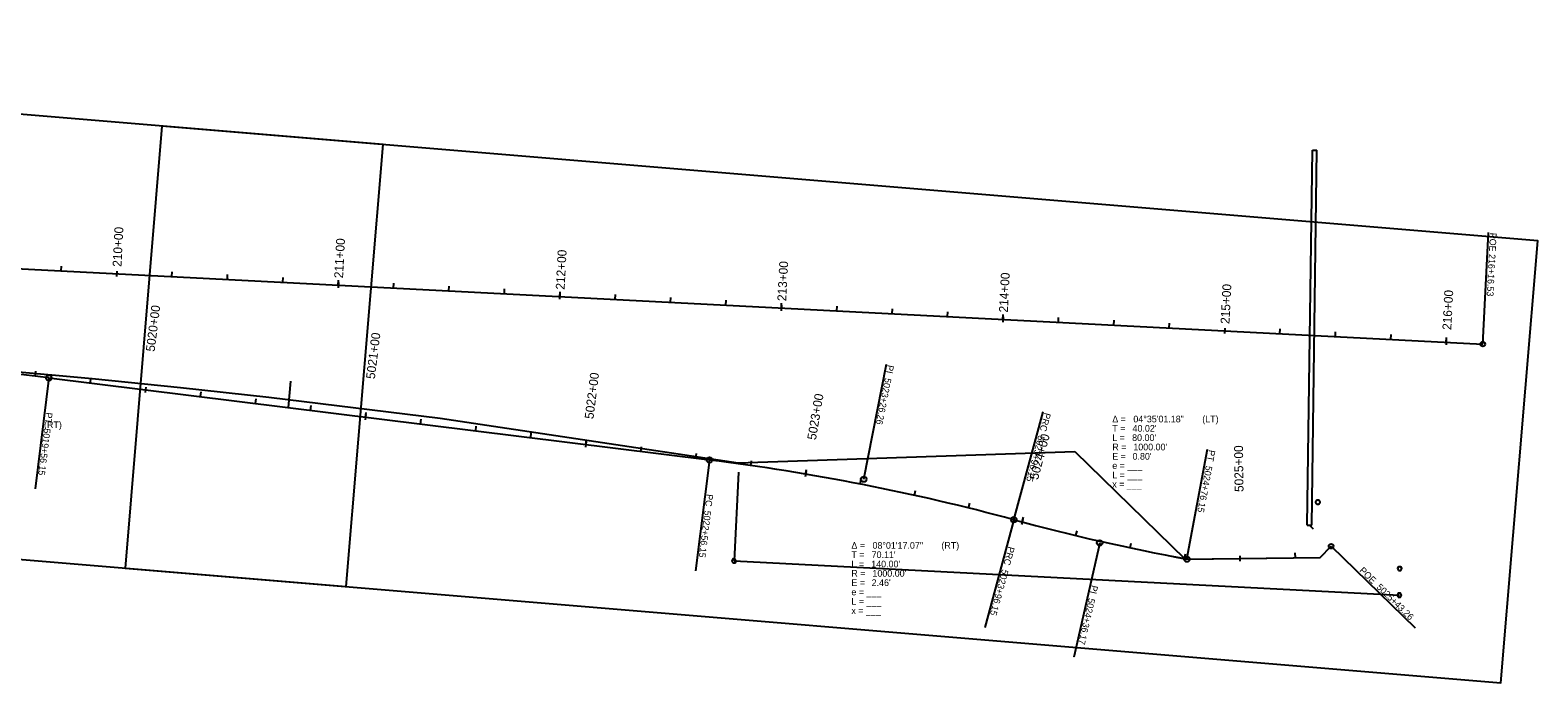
# Model space of a CAD drawing. Extents: x 20500393 to 20505339, y 7953466 to 7954298.
# Drawn here: x 20504659 to 20505339, y 7953466 to 7953761 of the extents above; entities that cross this region are included whole.
import ezdxf

# ---------------------------------------------------------------- set-up
doc = ezdxf.new("R2010")
doc.units = 0
for name, color, linetype in [('_CIVIL_CONSTRUCTION', 7, 'Continuous'), ('Alignment', 7, 'Continuous'), ('DisROW Proposed Temp Easements', 7, 'Continuous'), ('Draft_2', 7, 'Continuous'), ('Draft_3', 7, 'Continuous'), ('Draft_4', 7, 'Continuous'), ('Draft_7', 7, 'Continuous'), ('NamedBoundary', 7, 'Continuous'), ('RowProposed', 7, 'Continuous'), ('TextAlignment', 7, 'Continuous'), ('TextAlignmentLrg', 7, 'Continuous'), ('TextAlignmentSml', 7, 'Continuous'), ('Utility-Water - alignment', 7, 'Continuous')]:
    doc.layers.add(name, color=color, linetype=linetype)

msp = doc.modelspace()

# ---------------------------------------------------------------- linework, layer by layer
at = {"layer": '_CIVIL_CONSTRUCTION'}
for p, q in [((20504610.98, 7953655.19), (20505314.06, 7953618.94)), ((20504610.98, 7953655.19), (20505314.06, 7953618.94)), ((20504667.81, 7953603.76), (20504965.5, 7953566.69)), ((20505240.74, 7953522.73), (20505245.71, 7953527.82)), ((20505180.75, 7953521.98), (20505240.74, 7953522.73))]:
    msp.add_line(p, q, dxfattribs=at)
for centre, radius, start, end in [((20504421.91, 7951629.01), 1990, 82.90207, 85.23083), ((20504841.93, 7952574.35), 1000, 74.88066, 82.90207), ((20505363.59, 7954505.12), 1000, 254.88066, 259.46432)]:
    msp.add_arc(centre, radius, start, end, dxfattribs=at)
at = {"layer": 'Alignment'}
for p, q in [((20504667.81, 7953603.76), (20504965.5, 7953566.69)), ((20504667.81, 7953603.76), (20504965.5, 7953566.69)), ((20505240.74, 7953522.73), (20505245.71, 7953527.82)), ((20505240.74, 7953522.73), (20505245.71, 7953527.82)), ((20505180.75, 7953521.98), (20505240.74, 7953522.73)), ((20505180.75, 7953521.98), (20505240.74, 7953522.73))]:
    msp.add_line(p, q, dxfattribs=at)
for centre, radius, start, end in [((20504421.91, 7951629.01), 1990, 82.90207, 85.23083), ((20504421.91, 7951629.01), 1990, 82.90207, 85.23083), ((20504841.93, 7952574.35), 1000, 74.88066, 82.90207), ((20504841.93, 7952574.35), 1000, 74.88066, 82.90207), ((20505363.59, 7954505.12), 1000, 254.88066, 259.46432), ((20505363.59, 7954505.12), 1000, 254.88066, 259.46432)]:
    msp.add_arc(centre, radius, start, end, dxfattribs=at)
at = {"layer": 'DisROW Proposed Temp Easements'}
for p, q in [((20504978.65, 7953561.13), (20504976.6, 7953521.19)), ((20504976.6, 7953521.19), (20505276.45, 7953505.73))]:
    msp.add_line(p, q, dxfattribs=at)
at = {"layer": 'Draft_2'}
for p, q in [((20505129.73, 7953568.98), (20505129.73, 7953568.98)), ((20505012.37, 7953561.36), (20505012.37, 7953561.36))]:
    msp.add_line(p, q, dxfattribs=at)
at = {"layer": 'Draft_3'}
for p, q in [((20504667.81, 7953603.76), (20504965.5, 7953566.69)), ((20504775.82, 7953590.31), (20504776.82, 7953602.3))]:
    msp.add_line(p, q, dxfattribs=at)
msp.add_lwpolyline([(20505180.75, 7953521.98), (20505180.75, 7953521.98), (20505174.05, 7953523.22)], dxfattribs=at)
for centre, start, end in [((20504841.93, 7952574.35), 74.88066, 82.90207), ((20505363.59, 7954505.12), 254.88066, 259.46432)]:
    msp.add_arc(centre, 1000, start, end, dxfattribs=at)
at = {"layer": 'Draft_4'}
msp.add_line((20504667.81, 7953603.76), (20504965.5, 7953566.69), dxfattribs=at)
for centre, start, end in [((20504841.93, 7952574.35), 74.88066, 82.90207), ((20505363.59, 7954505.12), 254.88066, 259.46432)]:
    msp.add_arc(centre, 1000, start, end, dxfattribs=at)
at = {"layer": 'Draft_7'}
for p, q in [((20504647.49, 7953607.1), (20504687.32, 7953603.43)), ((20504687.32, 7953603.43), (20504727.12, 7953599.41)), ((20504727.12, 7953599.41), (20504766.88, 7953595.04)), ((20504766.88, 7953595.04), (20504844.2, 7953585.53)), ((20504844.2, 7953585.53), (20504978.5, 7953565.37)), ((20504978.5, 7953565.37), (20505130.25, 7953570.47)), ((20505130.25, 7953570.47), (20505179.97, 7953521.97)), ((20505240.74, 7953522.73), (20505245.71, 7953527.82)), ((20505179.97, 7953521.97), (20505240.74, 7953522.73))]:
    msp.add_line(p, q, dxfattribs=at)
at = {"layer": 'NamedBoundary'}
for points in [[(20504199.95, 7953760.54), (20504183.32, 7953561.23), (20504801.82, 7953509.62), (20504818.46, 7953708.92)], [(20504718.8, 7953717.24), (20504702.17, 7953517.93), (20505322.24, 7953466.19), (20505338.87, 7953665.49)]]:
    msp.add_lwpolyline(points, close=True, dxfattribs=at)
at = {"layer": 'RowProposed'}
for points in [[(20505239.2, 7953546.75), (20505240.22, 7953546.75), (20505240.72, 7953547.63), (20505240.22, 7953548.51), (20505239.2, 7953548.51), (20505238.69, 7953547.63)], [(20504976.04, 7953520.33), (20504977.06, 7953520.28), (20504977.61, 7953521.13), (20504977.15, 7953522.04), (20504976.13, 7953522.09), (20504975.58, 7953521.24)], [(20505276.08, 7953516.81), (20505277.09, 7953516.81), (20505277.6, 7953517.69), (20505277.09, 7953518.57), (20505276.08, 7953518.57), (20505275.57, 7953517.69)], [(20505275.9, 7953504.88), (20505276.91, 7953504.82), (20505277.46, 7953505.68), (20505277, 7953506.58), (20505275.99, 7953506.63), (20505275.43, 7953505.78)]]:
    msp.add_lwpolyline(points, close=True, dxfattribs=at)
at = {"layer": 'TextAlignment'}
for p, q in [((20505314.06, 7953618.94), (20505316.66, 7953669.27)), ((20505316.66, 7953669.27), (20505316.66, 7953669.27)), ((20505035.08, 7953558.02), (20505045.25, 7953609.83)), ((20505045.25, 7953609.83), (20505045.25, 7953609.83)), ((20504667.81, 7953603.76), (20504661.58, 7953553.74)), ((20505102.76, 7953539.74), (20505115.91, 7953588.39)), ((20505115.91, 7953588.39), (20505115.91, 7953588.39)), ((20505180.75, 7953521.98), (20505189.96, 7953571.53)), ((20505189.96, 7953571.53), (20505189.96, 7953571.53)), ((20504965.5, 7953566.69), (20504959.27, 7953516.67)), ((20504661.58, 7953553.74), (20504661.58, 7953553.74)), ((20505102.76, 7953539.74), (20505089.62, 7953491.08)), ((20505141.4, 7953529.3), (20505129.68, 7953477.81)), ((20505245.71, 7953527.82), (20505283.51, 7953490.95)), ((20504959.27, 7953516.67), (20504959.27, 7953516.67)), ((20505089.62, 7953491.08), (20505089.62, 7953491.08)), ((20505283.51, 7953490.95), (20505283.51, 7953490.95)), ((20505129.68, 7953477.81), (20505129.68, 7953477.81))]:
    msp.add_line(p, q, dxfattribs=at)
for centre, radius in [((20505314.06, 7953618.94), 1.07), ((20504667.81, 7953603.76), 1.25), ((20504965.5, 7953566.69), 1.25), ((20505035.08, 7953558.02), 1.25), ((20505102.76, 7953539.74), 1.25), ((20505102.76, 7953539.74), 1.25), ((20505141.4, 7953529.3), 1.25), ((20505245.71, 7953527.82), 1.07), ((20505180.75, 7953521.98), 1.25)]:
    msp.add_circle(centre, radius, dxfattribs=at)
at = {"layer": 'TextAlignmentLrg'}
for p, q in [((20504698.41, 7953651.9), (20504698.28, 7953649.46)), ((20504798.21, 7953645.53), (20504798.33, 7953647.71)), ((20504898.08, 7953640.38), (20504898.19, 7953642.57)), ((20504997.95, 7953635.24), (20504998.06, 7953637.42)), ((20505097.82, 7953630.09), (20505097.93, 7953632.27)), ((20505197.75, 7953626.16), (20505197.62, 7953623.72)), ((20505297.55, 7953619.79), (20505297.66, 7953621.97)), ((20504711.47, 7953599.55), (20504711.17, 7953597.12)), ((20504810.55, 7953585.98), (20504810.82, 7953588.15)), ((20504909.78, 7953573.63), (20504910.05, 7953575.79)), ((20505008.88, 7953560.32), (20505009.25, 7953562.47)), ((20505106.49, 7953538.74), (20505107.05, 7953540.85)), ((20505204.58, 7953523.5), (20505204.61, 7953521.05))]:
    msp.add_line(p, q, dxfattribs=at)
at = {"layer": 'TextAlignmentSml'}
for p, q in [((20504673.38, 7953651.97), (20504673.49, 7953654.15)), ((20504698.41, 7953651.9), (20504698.28, 7953649.46)), ((20504723.31, 7953649.39), (20504723.43, 7953651.58)), ((20504748.28, 7953648.11), (20504748.39, 7953650.29)), ((20504773.25, 7953646.82), (20504773.36, 7953649)), ((20504798.28, 7953646.76), (20504798.15, 7953644.31)), ((20504823.18, 7953644.25), (20504823.29, 7953646.43)), ((20504848.15, 7953642.96), (20504848.26, 7953645.14)), ((20504873.11, 7953641.67), (20504873.23, 7953643.85)), ((20504898.14, 7953641.61), (20504898.02, 7953639.16)), ((20504923.05, 7953639.1), (20504923.16, 7953641.28)), ((20504948.01, 7953637.81), (20504948.13, 7953639.99)), ((20504972.98, 7953636.52), (20504973.09, 7953638.7)), ((20504998.01, 7953636.46), (20504997.89, 7953634.01)), ((20505022.91, 7953633.95), (20505023.03, 7953636.13)), ((20505047.88, 7953632.66), (20505047.99, 7953634.84)), ((20505072.85, 7953631.37), (20505072.96, 7953633.55)), ((20505097.88, 7953631.31), (20505097.75, 7953628.86)), ((20505122.78, 7953628.8), (20505122.89, 7953630.98)), ((20505147.75, 7953627.51), (20505147.86, 7953629.69)), ((20505172.72, 7953626.23), (20505172.83, 7953628.41)), ((20505197.75, 7953626.16), (20505197.62, 7953623.72)), ((20505222.65, 7953623.65), (20505222.76, 7953625.83)), ((20505247.62, 7953622.36), (20505247.73, 7953624.54)), ((20505272.58, 7953621.08), (20505272.7, 7953623.26)), ((20505297.61, 7953621.01), (20505297.49, 7953618.57)), ((20504661.7, 7953604.51), (20504661.96, 7953606.68)), ((20504686.51, 7953601.43), (20504686.78, 7953603.59)), ((20504711.47, 7953599.55), (20504711.17, 7953597.12)), ((20504736.12, 7953595.25), (20504736.39, 7953597.42)), ((20504760.93, 7953592.16), (20504761.2, 7953594.33)), ((20504785.74, 7953589.07), (20504786.01, 7953591.24)), ((20504810.7, 7953587.2), (20504810.4, 7953584.77)), ((20504835.36, 7953582.89), (20504835.63, 7953585.06)), ((20504860.17, 7953579.8), (20504860.44, 7953581.97)), ((20504884.98, 7953576.71), (20504885.25, 7953578.88)), ((20504909.93, 7953574.84), (20504909.63, 7953572.41)), ((20504934.59, 7953570.54), (20504934.86, 7953572.7)), ((20504959.4, 7953567.45), (20504959.67, 7953569.61)), ((20504984.19, 7953564.18), (20504984.5, 7953566.34)), ((20505009.09, 7953561.52), (20505008.68, 7953559.11)), ((20505033.48, 7953555.83), (20505033.9, 7953557.98)), ((20505057.95, 7953550.74), (20505058.43, 7953552.87)), ((20505082.29, 7953545.03), (20505082.82, 7953547.15)), ((20505106.8, 7953539.92), (20505106.17, 7953537.55)), ((20505130.72, 7953532.61), (20505131.23, 7953534.74)), ((20505155.11, 7953527.1), (20505155.56, 7953529.23)), ((20505179.62, 7953522.19), (20505180.02, 7953524.34)), ((20505204.58, 7953523.5), (20505204.61, 7953521.05)), ((20505229.6, 7953522.59), (20505229.57, 7953524.77))]:
    msp.add_line(p, q, dxfattribs=at)
at = {"layer": 'Utility-Water - alignment'}
for p, q in [((20505234.98, 7953537.29), (20505237.33, 7953706.46)), ((20505236.98, 7953537.26), (20505239.33, 7953706.43)), ((20505237.33, 7953706.46), (20505239.33, 7953706.43)), ((20505234.98, 7953537.29), (20505236.98, 7953537.26)), ((20505237.81, 7953535.5), (20505235.98, 7953537.27))]:
    msp.add_line(p, q, dxfattribs=at)

# ---------------------------------------------------------------- texts
at = {"layer": 'TextAlignment'}
for s, rotation, p in [('POE ', 267.04866, (20505317.31, 7953669.24)), ('216+16.53', 267.04866, (20505316.82, 7953659.62)), ('PI ', 258.89136, (20505045.78, 7953609.73)), ('5023+26.26', 258.89136, (20505044.63, 7953603.86)), ('PT', 262.90207, (20504666.54, 7953588.29)), ('PRC', 254.88066, (20505116.55, 7953588.22)), ('5019+56.15', 262.90207, (20504665.65, 7953581.09)), ('5023+96.15', 254.88066, (20505113.77, 7953577.95)), ('PT', 259.46432, (20505190.61, 7953571.41)), ('5024+76.15', 259.46432, (20505189.28, 7953564.27)), ('PC', 262.90207, (20504964.26, 7953551.43)), ('5022+56.15', 262.90207, (20504963.34, 7953544.02)), ('PRC', 254.88066, (20505100.24, 7953527.86)), ('5023+96.15', 254.88066, (20505097.46, 7953517.59)), ('POE ', 315.71393, (20505258.19, 7953516.56)), ('PI ', 257.17249, (20505137.77, 7953510.41)), ('5025+43.26', 315.71393, (20505265.9, 7953509.05)), ('5024+36.17', 257.17249, (20505136.45, 7953504.58))]:
    msp.add_text(s, height=3, rotation=rotation, dxfattribs=at).set_placement(p)
for s, p in [(' (RT)', (20504664.54, 7953581.06)), ('T = ', (20505147.08, 7953579.46)), ('Δ = ', (20505147.08, 7953583.66)), ("40.02'", (20505156.21, 7953579.46)), ('04°35\'01.18"', (20505156.58, 7953583.66)), (' (LT)', (20505186.52, 7953583.66)), ('L = ', (20505147.08, 7953575.26)), ("80.00'", (20505156.02, 7953575.26)), ('R = ', (20505147.08, 7953571.06)), ('E = ', (20505147.08, 7953566.86)), ("0.80'", (20505156.21, 7953566.86)), ("1000.00'", (20505156.57, 7953571.06)), ('e = ___ ', (20505147.08, 7953562.66)), ('L = ___', (20505147.08, 7953558.46)), ('x = ___', (20505147.08, 7953554.26)), ('Δ = ', (20505029.51, 7953526.66)), ('08°01\'17.07"', (20505039.01, 7953526.66)), (' (RT)', (20505068.95, 7953526.66)), ('T = ', (20505029.51, 7953522.46)), ('L = ', (20505029.51, 7953518.26)), ("140.00'", (20505038.44, 7953518.26)), ("70.11'", (20505038.63, 7953522.46)), ('R = ', (20505029.51, 7953514.06)), ("1000.00'", (20505038.99, 7953514.06)), ('e = ___ ', (20505029.51, 7953505.66)), ('E = ', (20505029.51, 7953509.86)), ("2.46'", (20505038.63, 7953509.86)), ('L = ___', (20505029.51, 7953501.46)), ('x = ___', (20505029.51, 7953497.26))]:
    msp.add_text(s, height=3, dxfattribs=at).set_placement(p)
at = {"layer": 'TextAlignmentLrg'}
msp.add_text('5025+00', height=4.008, rotation=90.71432, dxfattribs=at).set_placement((20505206.23, 7953552.3))
at = {"layer": 'TextAlignmentSml'}
for s, rotation, p in [('210+00', 87.04866, (20504700.51, 7953653.71)), ('211+00', 87.04866, (20504800.38, 7953648.56)), ('212+00', 87.04866, (20504900.24, 7953643.41)), ('213+00', 87.04866, (20505000.11, 7953638.26)), ('214+00', 87.04866, (20505099.98, 7953633.11)), ('215+00', 87.04866, (20505199.85, 7953627.96)), ('216+00', 87.04866, (20505299.84, 7953625.25)), ('5020+00', 82.90207, (20504715.46, 7953615.38)), ('5021+00', 82.90207, (20504814.69, 7953603.02)), ('5022+00', 82.90207, (20504913.22, 7953585.01)), ('5023+00', 80.38943, (20505013.49, 7953575.51)), ('5024+00', 75.10147, (20505113.57, 7953557.55)), ('5025+00', 90.71432, (20505206.23, 7953552.3))]:
    msp.add_text(s, height=4.008, rotation=rotation, dxfattribs=at).set_placement(p)

doc.saveas('drawing.dxf')
